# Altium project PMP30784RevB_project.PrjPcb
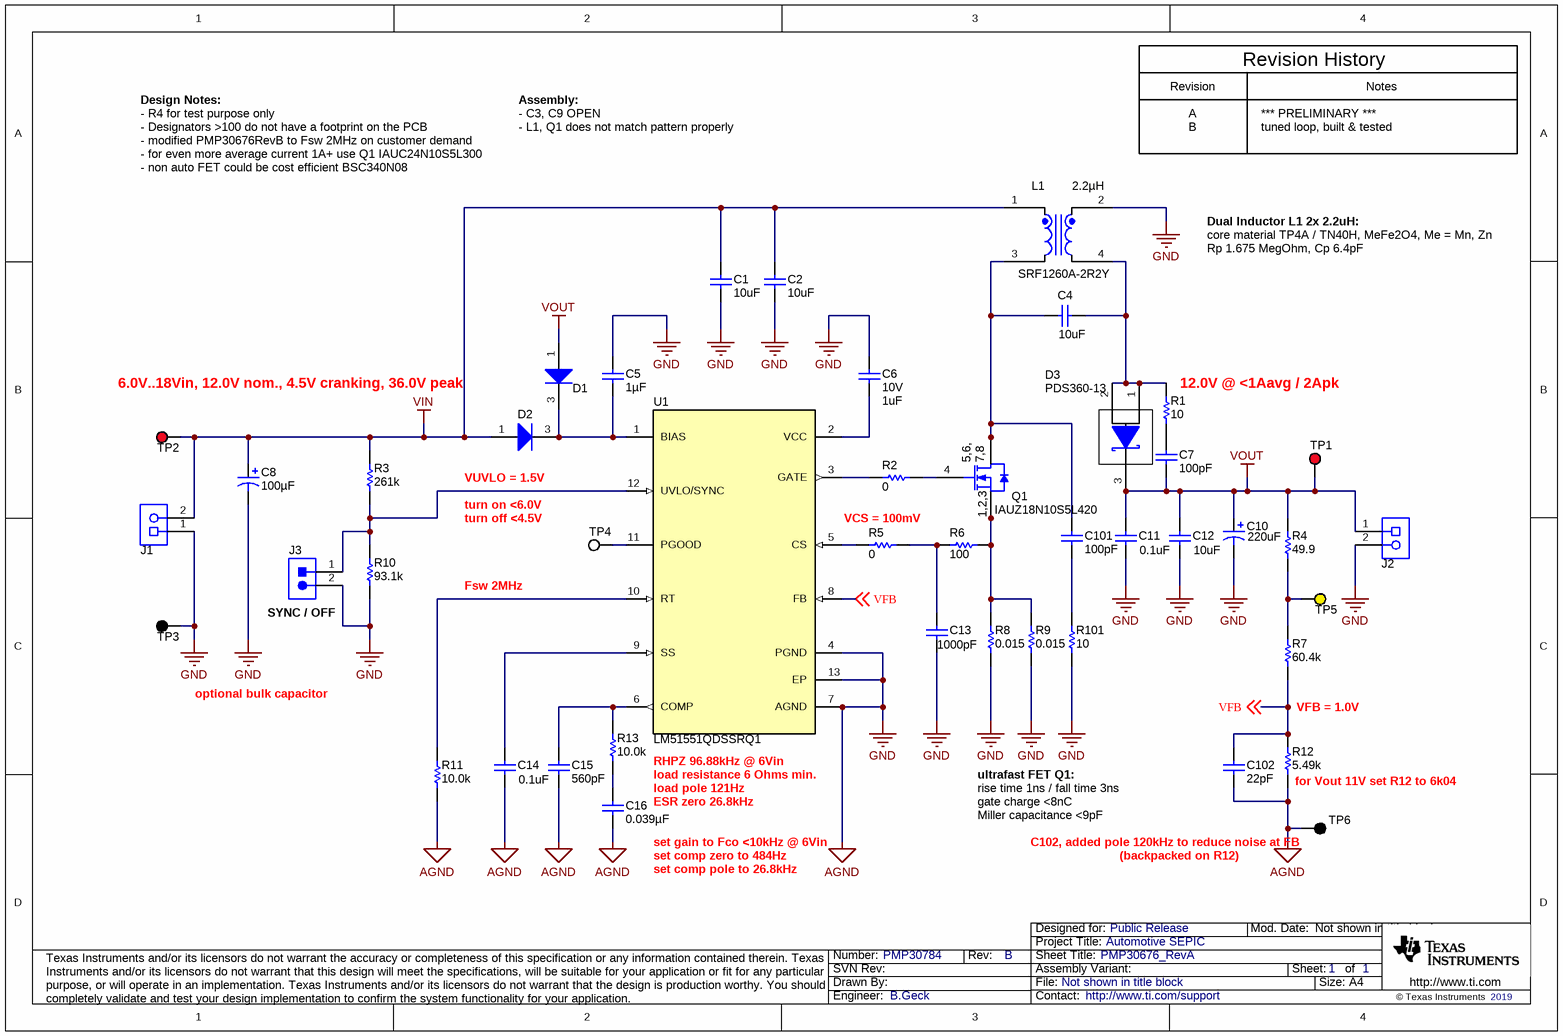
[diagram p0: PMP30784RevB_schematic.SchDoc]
CopyrightYear: 2019; PCB_Layout: M.Zehendner; PCB_Rev: A; PRJ_Customer: Public Release; PRJ_Engineer: B.Geck; PRJ_Number: PMP30784; PRJ_Title: Automotive SEPIC; SCH_Rev: B; TechSupport: http://www.ti.com/support; TID: N/A
1 sheet, 45 parts. Net scope: global (net labels, ports and power ports of the same name join across sheets).
Board file: PMP30676_board.PcbDoc

## Sheet PMP30784RevB_schematic.SchDoc: PMP30676_RevA
size A4; Date: Not shown in title block; ApprovedBy: Not shown in title block; CheckedBy: Not shown in title block; Author: Not shown in title block; CompanyName: Not shown in title block; Engineer: Not shown in title block; Organization: Not shown in title block; Address1: Not shown in title block; Address2: Not shown in title block; Address3: Not shown in title block; Address4: Not shown in title block; DocumentNumber: 1; Revision: Use project parameter SCH_Rev; SheetNumber: 1; SheetTotal: 1; PageSetup: Record=PageOptions¦CenterHorizontal=True¦CenterVertical=True¦PrintScale=0.70¦XCorrection=1.00¦YCorrection=1.00¦PrintKind=0¦BorderSize=5000000¦LeftOffset=0¦BottomOffset=0¦Orientation=2¦PaperLength=1000¦PaperWidth=1000¦Scale=100¦PaperSource=15¦PrintQuality=600¦MediaType=1¦DitherType=10¦PaperKind=A4¦PrintScaleMode=1

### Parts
C1  ValueDisplayed: 10uF  [1210_270]  (hidden comment: GRM32ER71H106KA12L)
C2  ValueDisplayed: 10uF  [1210_270]  (hidden comment: GRM32ER71H106KA12L)
C4  ValueDisplayed: 10uF  [1210_270]  (hidden comment: GRM32ER71H106KA12L)
C5  Cap_F: 1µF  [0805_HV]  (hidden comment: GRM21BR71H105KA12L)
C6  VDC_V: 10V  ValueDisplayed: 1uF  [0805_HV]  (hidden comment: GRM21BR71A105KA01L)
C7  ValueDisplayed: 100pF  [0603]  (hidden comment: GCM1885C2A101JA16D)
C8  ValueDisplayed: 100µF  [Panasonic_G]  (hidden comment: EEH-ZC1H101P)
C10  ValueDisplayed: 220uF  [HXB_HA0]  (hidden comment: HHXC250ARA221MHA0G)
C11  ValueDisplayed: 0.1uF  [0402]  (hidden comment: GRM155R71H104ME14D)
C12  ValueDisplayed: 10uF  [1210_220]  (hidden comment: GRM32DR71E106KA12L)
C13  ValueDisplayed: 1000pF  [0402]  (hidden comment: GRM155R61E102KA01D)
C14  ValueDisplayed: 0.1uF  [0402]  (hidden comment: GRM155R71C104KA88D)
C15  ValueDisplayed: 560pF  [0603]  (hidden comment: GRM1885C1E561JA01D)
C16  ValueDisplayed: 0.039µF  [0603]  (hidden comment: GRM188R71E393KA01D)
C101  ValueDisplayed: 100pF  [0603]  (hidden comment: GCM1885C2A101JA16D)
C102  ValueDisplayed: 22pF  [0603]  (hidden comment: GRM1885C1H220JA01D)
D1  BAS16LT1G  [SOT-23]  (value not drawn)
D2  BAS16LT1G  [SOT-23]  (value not drawn)
D3  PDS360-13  [PowerDI5]
J1  ED120/2DS  [On-Shore_ED120_2DS]  (value not drawn)
J2  ED120/2DS  [On-Shore_ED120_2DS]  (value not drawn)
J3  TSW-102-07-G-S  [TSW-102-07-G-S]  (value not drawn)
L1  SRF1260A-2R2Y  ValueDisplayed: 2.2µH  [SRF1260A]
Q1  IAUZ18N10S5L420  [PG-TSDSON-8FL]
R1  ValueDisplayed: 10  [0805_HV]  (hidden comment: CRCW080510R0JNEA)
R2  ValueDisplayed: 0  [0603]  (hidden comment: ERJ-3GEY0R00V)
R3  ValueDisplayed: 261k  [0603]  (hidden comment: CRCW0603261KFKEA)
R4  ValueDisplayed: 49.9  [0603]  (hidden comment: CRCW060349R9FKEA)
R5  ValueDisplayed: 0  [0603]  (hidden comment: ERJ-3GEY0R00V)
R6  ValueDisplayed: 100  [0603]  (hidden comment: CRCW0603100RFKEA)
R7  ValueDisplayed: 60.4k  [0603]  (hidden comment: CRCW060360K4FKEA)
R8  ValueDisplayed: 0.015  [1206]  (hidden comment: CSR1206FK15L0)
R9  ValueDisplayed: 0.015  [1206]  (hidden comment: CSR1206FK15L0)
R10  ValueDisplayed: 93.1k  [0603]  (hidden comment: CRCW060393K1FKEA)
R11  ValueDisplayed: 10.0k  [0603]  (hidden comment: CRCW060310K0FKEA)
R12  ValueDisplayed: 5.49k  [0603]  (hidden comment: CRCW06035K49FKEA)
R13  ValueDisplayed: 10.0k  [0603]  (hidden comment: CRCW060310K0FKEA)
R101  ValueDisplayed: 10  [0603]  (hidden comment: CRCW060310R0JNEAHP)
TP1  5010  [Keystone5010]  (value not drawn)
TP2  5010  [Keystone5010]  (value not drawn)
TP3  5011  [Keystone5011]  (value not drawn)
TP4  5012  [Keystone5012]  (value not drawn)
TP5  5014  [Keystone5014]  (value not drawn)
TP6  5011  [Keystone5011]  (value not drawn)
U1  LM51551QDSSRQ1  [DSS0012C]

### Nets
AGND: C1.2 C2.2 C5.1 C6.2 C8.2(-) C10.2(-) C11.2 C12.2 C13.2 C14.2 C15.2 C16.2 C102.2 J1.1 J2.2 J3.2 L1.2 R8.1 R9.1 R10.1 R11.1 R12.1 R101.1 TP3.1 TP6.1 U1.4(PGND) U1.7(AGND) U1.13(EP)  [also labelled GND]
VIN: C1.1 C2.1 C8.1(+) D2.1(A) J1.2 L1.1 R3.2 TP2.1
VOUT: C7.2 C10.1(+) C11.1 C12.1 D1.1(A) D3.3(K) J2.1 R4.2 TP1.1
VFB: C102.1 R7.1 R12.2 U1.8(FB) ; off-sheet VFB
NetC4_1: C4.1 D3.1(A) D3.2(A) L1.4 R1.2
NetC4_2: C4.2 C101.1 L1.3 Q1.5(D) Q1.6(D) Q1.7(D) Q1.8(D) Q1.9(D)
NetC5_2: C5.2 D1.3(K) D2.3(K) U1.1(BIAS)
NetC6_1: C6.1 U1.2(VCC)
NetC7_1: C7.1 R1.1
NetC13_1: C13.1 R5.2 R6.1
NetC14_1: C14.1 U1.9(SS)
NetC15_1: C15.1 R13.2 U1.6(COMP)
NetC16_1: C16.1 R13.1
NetC101_2: C101.2 R101.2
NetJ3_1: J3.1 R3.1 R10.2 U1.12(UVLO/SYNC)
NetQ1_1: Q1.1(S) Q1.2(S) Q1.3(S) R6.2 R8.2 R9.2
NetQ1_4: Q1.4(G) R2.2
NetR2_1: R2.1 U1.3(GATE)
NetR4_1: R4.1 R7.2 TP5.1
NetR5_1: R5.1 U1.5(CS)
NetR11_2: R11.2 U1.10(RT)
NetTP4_1: TP4.1 U1.11(PGOOD)

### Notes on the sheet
- Design Notes:
- - R4 for test purpose only
- Assembly:
- - C3, C9 OPEN
- Revision
- A
- *** PRELIMINARY ***
- Revision History
- Notes
- - Designators >100 do not have a footprint on the PCB
- - modified PMP30676RevB to Fsw 2MHz on customer demand
- - for even more average current 1A+ use Q1 IAUC24N10S5L300
- - non auto FET could be cost efficient BSC340N08
- - L1, Q1 does not match pattern properly
- B
- tuned loop, built & tested
- Dual Inductor L1 2x 2.2uH:
- core material TP4A / TN40H, MeFe2O4, Me = Mn, Zn
- Rp 1.675 MegOhm, Cp 6.4pF
- 6.0V..18Vin, 12.0V nom., 4.5V cranking, 36.0V peak
- (near R1) 12.0V @ <1Aavg / 2Apk
- (near D2) VUVLO = 1.5V
- turn on <6.0V
- turn off <4.5V
- VCS = 100mV
- Fsw 2MHz
- (near J3) SYNC / OFF
- optional bulk capacitor
- VFB = 1.0V
- RHPZ 96.88kHz @ 6Vin
- load resistance 6 Ohms min.
- load pole 121Hz
- ultrafast FET Q1:
- rise time 1ns / fall time 3ns
- (near R12) for Vout 11V set R12 to 6k04
- (near C16) set gain to Fco <10kHz @ 6Vin
- (near C16) set comp zero to 484Hz
- ESR zero 26.8kHz
- gate charge <8nC
- Miller capacitance <9pF
- (backpacked on R12)
- (near TP6) C102, added pole 120kHz to reduce noise at FB
- set comp pole to 26.8kHz

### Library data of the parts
C1 C2 C4 = CMP-0009226-3: CAP, CERM, 10 uF, 50 V, +/- 10%, X7R, 1210; Manufacturer: MuRata; TaMin_C: -55°C; Polarized: N; SizeAreaWB_mm2: 14.7; Value1: Unknown; U/M: EA; Value: 10uF; TaMax_C: 125°C; SizeZ_mm: 2.7; SizeX_mm: 3.2; SizeY_mm: 2.5; Cap_Case: 1210; Value2: 50V; SizeArea_mm2: 8; Cap_F: 10µF; AEC Category: Q200
C5 = CMP-0008350-2: CAP, CERM, 1 uF, 50 V, +/- 10%, X7R, 0805; Manufacturer: MuRata; TaMin_C: -55°C; Polarized: N; SizeAreaWB_mm2: 6.75; Value1: Unknown; U/M: EA; Value: 1uF; TaMax_C: 125°C; SizeZ_mm: 1.45; SizeX_mm: 2; SizeY_mm: 1.25; Cap_Case: 0805; Value2: 50V; SizeArea_mm2: 2.5; AEC Category: Q200
C6 = CMP-0008313-2: CAP, CERM, 1 uF, 10 V, +/- 10%, X7R, 0805; Manufacturer: MuRata; TaMin_C: -55°C; ESR_ohm: 7m; Polarized: N; SizeAreaWB_mm2: 6.75; Value1: 0.007 ohm; U/M: EA; Value: 1uF; TaMax_C: 125°C; SizeZ_mm: 1.45; SizeX_mm: 2; SizeY_mm: 1.25; Cap_Case: 0805; SizeArea_mm2: 2.5; Cap_F: 1µF; AEC Category: Q200
C7 C101 = GCM1885C2A101JA16D: CAP, CERM, 100 pF, 100 V,+/- 5%, C0G/NP0, AEC-Q200 Grade 1, 0603; Manufacturer: MuRata; Polarized: N; CompType: Capacitor; Value: 100pF; U/M: EA; Cap_F: 0.0000000001; Tolerance_%: 5; VDC_V: 100; Value2: 100V; TaMin_C: -55; TaMax_C: 125; SizeArea_mm2: 1.28; SizeAreaWB_mm2: 4.68; SizeX_mm: 1.6; SizeY_mm: 0.8; SizeZ_mm: 1; AEC Category: Q200; AEC Qualified: Y
C8 = EEH-ZC1H101P: CAP, Polymer Hybrid, 100 µF, 50 V,+/- 20%, 0.028 ohm, AEC-Q200 Grade 1, D10xL10.2mm SMD; Manufacturer: Panasonic; Polarized: Y; CompType: Capacitor; Value: 100uF; U/M: EA; Cap_F: 0.0001; Tolerance_%: 20; VDC_V: 50; Value2: 50V; ESR_ohm: 0.028; IRMS_A: 1.6; TaMin_C: -55; TaMax_C: 125; Cap_Case: 10x10.2mm; SizeAreaWB_mm2: 151.29; SizeArea_mm2: 106.09; SizeX_mm: 10.3; SizeZ_mm: 10.5; AEC Category: Q200; AEC Grade: 1
C10 = CMP-0012270-3: CAP, Aluminum Polymer, 220 uF, 25 V, +/- 20%, 0.027 ohm, AEC-Q200 Grade 2, D8xL10mm SMD; Manufacturer: Chemi-Con; TaMin_C: -55°C; ESR_ohm: 0.03; Polarized: Y; SizeAreaWB_mm2: 113.3; Value: 220uF; TaMax_C: 105°C; SizeZ_mm: 10.5; SizeX_mm: 9; SizeY_mm: 8.3; Cap_Case: HA0; Value2: 25V; SizeArea_mm2: 74.7; CompType: Capacitor; Cap_F: 220µF; IRMS_A: 1.6A; AEC Grade: 2; AEC Category: Q200
C11 = CMP-0006675-2: CAP, CERM, 0.1 uF, 50 V, +/- 20%, X7R, 0402; Manufacturer: MuRata; TaMin_C: -55°C; Polarized: N; SizeAreaWB_mm2: 3; Value1: Unknown; U/M: EA; Value: 0.1uF; TaMax_C: 125°C; SizeZ_mm: 0.6; SizeX_mm: 1; SizeY_mm: 0.5; Value2: 50V; Cap_F: 100nF; AEC Category: Q200
C12 = CMP-0009190-2: CAP, CERM, 10 uF, 25 V, +/- 10%, X7R, 1210; Manufacturer: MuRata; TaMin_C: -55°C; Polarized: N; SizeAreaWB_mm2: 14.7; Value1: Unknown; U/M: EA; Value: 10uF; TaMax_C: 125°C; SizeZ_mm: 2.2; SizeX_mm: 3.2; SizeY_mm: 2.5; Cap_Case: 1210; Value2: 25V; SizeArea_mm2: 8; Cap_F: 10µF; AEC Category: Q200
C13 = CMP-0006606-2: CAP, CERM, 1000 pF, 25 V, +/- 10%, X5R, 0402; Manufacturer: MuRata; TaMin_C: -55°C; Polarized: N; SizeAreaWB_mm2: 3; Value1: Unknown; U/M: EA; Value: 1000pF; TaMax_C: 85°C; SizeZ_mm: 0.6; SizeX_mm: 1; SizeY_mm: 0.5; Value2: 25V; Cap_F: 1nF; AEC Category: Q200
C14 = CMP-0006641-2: CAP, CERM, 0.1 uF, 16 V, +/- 10%, X7R, 0402; Manufacturer: MuRata; TaMin_C: -55°C; Polarized: N; SizeAreaWB_mm2: 3; Value1: Unknown; U/M: EA; Value: 0.1uF; TaMax_C: 125°C; SizeZ_mm: 0.6; SizeX_mm: 1; SizeY_mm: 0.5; Value2: 16V; Cap_F: 100nF; AEC Category: Q200
C15 = GRM1885C1E561JA01D: CAP, CERM, 560 pF, 25 V,+/- 5%, C0G/NP0, 0603; Manufacturer: MuRata; Polarized: N; CompType: Capacitor; Value: 560pF; U/M: EA; Cap_F: 0.00000000056; Tolerance_%: 5; VDC_V: 25; Value2: 25V; TaMin_C: -55; TaMax_C: 125; SizeArea_mm2: 1.28; SizeAreaWB_mm2: 4.68; SizeX_mm: 1.6; SizeY_mm: 0.8; SizeZ_mm: 1; AEC Category: Q200
C16 = GRM188R71E393KA01D: CAP, CERM, 0.039 µF, 25 V,+/- 10%, X7R, 0603; Manufacturer: MuRata; Polarized: N; CompType: Capacitor; Value: 0.039uF; U/M: EA; Cap_F: 0.000000039; Tolerance_%: 10; VDC_V: 25; Value2: 25V; TaMin_C: -55; TaMax_C: 125; SizeArea_mm2: 1.28; SizeAreaWB_mm2: 4.68; SizeX_mm: 1.6; SizeY_mm: 0.8; SizeZ_mm: 1; AEC Category: Q200
C102 = GRM1885C1H220JA01D: CAP, CERM, 22 pF, 50 V,+/- 5%, C0G/NP0, 0603; Manufacturer: MuRata; Polarized: N; CompType: Capacitor; Value: 22pF; U/M: EA; Cap_F: 0.000000000022; Tolerance_%: 5; VDC_V: 50; Value2: 50V; TaMin_C: -55; TaMax_C: 125; SizeArea_mm2: 1.28; SizeAreaWB_mm2: 4.68; SizeX_mm: 1.6; SizeY_mm: 0.8; SizeZ_mm: 1; AEC Category: Q200; Green_Lifecycle: Active; Green_REACh: Passed
D1 D2 = CMP-0029193-2: Diode, Switching, 100 V, 0.2 A, SOT-23; Manufacturer: ON Semiconductor; Value: 100V; Green_Lifecycle: Active; SizeAreaWB_mm2: 14; Vf_V: 1.25V; SizeZ_mm: 1.1; AEC Qualified: N; SizeX_mm: 2.5; Green_REACh: Passed; AEC Category: Q101; Value1: 0.2A; SizeY_mm: 3; SizeArea_mm2: 7.5; Io_A: 200mA; TJmax_C: 150°C
D3 = PDS360-13: Diode, Schottky, 60 V, 3 A, PowerDI5; Manufacturer: Diodes Inc.; U/M: EA; Vf_V: 0.62; Value: 60V; Value1: 3A; Value2: 0.62V; Io_A: 3; Vr_V: 60; TJmax_C: 150; SizeAreaWB_mm2: 49.56; SizeArea_mm2: 24.96; SizeX_mm: 6.4; SizeY_mm: 3.9; SizeZ_mm: 1.05; AEC Category: Q101; Green_Lifecycle: Active; Green_REACh: Passed
J1 J2 = CMP-0074910-1: Terminal Block, 5.08 mm, 2x1, Brass, TH; Manufacturer: On-Shore Technology; Cert_VDE: Y; CNHeader: False; Current_A: 15A; Green_Lifecycle: Not Set; Shrouded: N; Gender: Female; Green_REACh: Incomplete; Voltage_V: 300V; Row_Count: 1; Pitch_mm: 5.08; CT: True
J3 = CMP-0075405-2: Header, 100mil, 2x1, Gold, TH; Manufacturer: Samtec; Pitch_mm: 2.54; Cert_VDE: N; Gender: Male; Cert_CSA: Y; Voltage_V: 550V; Green_REACh: Passed; Current_A: 6.3A; Green_Lifecycle: Active; Row_Count: 1
L1 = SRF1260A-331M: Coupled inductor, 2.2 µH, 5.44A, 0.009 ohm, AEC-Q200 Grade 1, SMD; Manufacturer: Bourns; SymbolCreator: a0412235; SizeAreaWB_mm2: 210.25; SizeArea_mm2: 156.25; SizeX_mm: 12.5; SizeZ_mm: 6.2; Value: 2.2uH; Ind_H: 2.2E-6; DCR_ohm: 0.009; AEC Category: Q200; AEC Qualified: Y; AEC Grade: 1
Q1 = BSZ013NE2LS5IATMA1: MOSFET, N-CH, 100 V, 40 A, 8-PG-TSDSON; Manufacturer: Infineon Technologies; Alternate Manufacturer: None; U/M: EA; ChType: N; Value: 100V; VdsMax_V: 100; Value1: 0.055 ohm; Rdson45_ohm: 0.055; Value2: 5.4 nC; QgTyp_nC: 5.4; Vgs_V: 20; IdsMax_A: 18; SizeAreaWB_mm2: 18.49; SizeArea_mm2: 10.89; SizeX_mm: 3.3; SizeZ_mm: 1.1; AEC Category: Q101; AEC Qualified: Y; Green_Lifecycle: Active; Green_REACh: Passed
R1 = CRCW080510R0JNEA: RES, 10, 5%, 0.125 W, 0805; Manufacturer: Vishay-Dale; CompType: Resistor; Value: 10; Value_Code: 10R0; Tolerance_%: 5; Power_W: 0.125; Value2: 0.125W; VDC_V: 150; TempCo: 200 ppm/C; SizeArea_mm2: 2.5; SizeX_mm: 2; SizeY_mm: 1.25; SizeZ_mm: 1.45; EIA_Code: E24; U/M: EA; AEC Category: Q200; Green_Lifecycle: Active; Green_REACh: Passed
R2 R5 = CMP-0025874-4: RES, 0, 5%, 0.1 W, AEC-Q200 Grade 0, 0603; Manufacturer: Panasonic; Power_W: 100mW; TempCo: 600 ppm/C; Value_Code: 0000; Value: 0; EIA_Code: E24; SizeX_mm: 1.6; SizeY_mm: 0.8; SizeZ_mm: 1; Value2: 0.1W; SizeArea_mm2: 1.28; AEC Qualified: Y; VDC_V: 50V; AEC Category: Q200; SizeAreaWB_mm2: 4.68
R3 = CMP-0022244-4: RES, 261 k, 1%, 0.1 W, AEC-Q200 Grade 0, 0603; Manufacturer: Vishay-Dale; Power_W: 100mW; TempCo: 100 ppm/C; Value: 261k; EIA_Code: E96; SizeX_mm: 1.6; SizeY_mm: 0.8; SizeZ_mm: 1; Value2: 0.1W; SizeArea_mm2: 1.28; AEC Qualified: Y; VDC_V: 75V; AEC Category: Q200; AEC Grade: 0
R4 = CMP-0022448-4: RES, 49.9, 1%, 0.1 W, AEC-Q200 Grade 0, 0603; Manufacturer: Vishay-Dale; Power_W: 100mW; TempCo: 100 ppm/C; Value_Code: 49R9; Value: 49.9; EIA_Code: E96; SizeX_mm: 1.6; SizeY_mm: 0.8; SizeZ_mm: 1; Value2: 0.1W; SizeArea_mm2: 1.28; AEC Qualified: Y; VDC_V: 75V; AEC Category: Q200; AEC Grade: 0
R6 = CMP-0021991-2: RES, 100, 1%, 0.1 W, 0603; Manufacturer: Vishay-Dale; Power_W: 100mW; TempCo: 100 ppm/C; Value_Code: 100R; U/M: EA; Value: 100; EIA_Code: E96; SizeX_mm: 1.6; SizeY_mm: 0.8; SizeZ_mm: 1; Value2: 0.1W; SizeArea_mm2: 1.28; VDC_V: 75V; AEC Category: Q200
R7 = CMP-0022532-4: RES, 60.4 k, 1%, 0.1 W, AEC-Q200 Grade 0, 0603; Manufacturer: Vishay-Dale; Power_W: 100mW; TempCo: 100 ppm/C; Value_Code: 60k4; Value: 60.4k; EIA_Code: E96; SizeX_mm: 1.6; SizeY_mm: 0.8; SizeZ_mm: 1; Value2: 0.1W; SizeArea_mm2: 1.28; AEC Qualified: Y; VDC_V: 75V; AEC Category: Q200; AEC Grade: 0
R8 R9 = CMP-0017258-2: RES, 0.015, 1%, 0.5 W, 1206; Manufacturer: Stackpole Electronics Inc; Power_W: 500mW; TempCo: 100 ppm/C; Value_Code: R015; U/M: EA; Value: 0.015; EIA_Code: E96; SizeX_mm: 3.2; SizeY_mm: 1.6; SizeZ_mm: 1.35; Value2: 0.5W; SizeArea_mm2: 5.12; AEC Category: Q200
R10 = CMP-0022655-4: RES, 93.1 k, 1%, 0.1 W, AEC-Q200 Grade 0, 0603; Manufacturer: Vishay-Dale; Power_W: 100mW; TempCo: 100 ppm/C; Value_Code: 93k1; Value: 93.1k; EIA_Code: E96; SizeX_mm: 1.6; SizeY_mm: 0.8; SizeZ_mm: 1; Value2: 0.1W; SizeArea_mm2: 1.28; AEC Qualified: Y; VDC_V: 75V; AEC Category: Q200; AEC Grade: 0
R11 R13 = CRCW060310K0FKEA: RES, 10.0 k, 1%, 0.1 W, 0603; Manufacturer: Vishay-Dale; CompType: Resistor; Value: 10.0k; Res_ohm: 10000; Value_Code: 10k0; Tolerance_%: 1; Power_W: 0.1; Value2: 0.1W; VDC_V: 75; TempCo: 100 ppm/C; SizeArea_mm2: 1.28; SizeX_mm: 1.6; SizeY_mm: 0.8; EIA_Code: E96; U/M: EA; AEC Category: Q200; Green_Lifecycle: Active; Green_REACh: Passed
R12 = CMP-0022512-4: RES, 5.49 k, 1%, 0.1 W, AEC-Q200 Grade 0, 0603; Manufacturer: Vishay-Dale; Power_W: 100mW; TempCo: 100 ppm/C; Value_Code: 5k49; Value: 5.49k; EIA_Code: E96; SizeX_mm: 1.6; SizeY_mm: 0.8; SizeZ_mm: 1; Value2: 0.1W; SizeArea_mm2: 1.28; AEC Qualified: Y; VDC_V: 75V; AEC Category: Q200; AEC Grade: 0
R101 = CRCW060310R0JNEAHP: RES, 10, 5%, 0.25 W, 0603; Manufacturer: Vishay-Dale; CompType: Resistor; Value: 10; Value_Code: 10R0; Tolerance_%: 5; Power_W: 0.25; Value2: 0.25W; VDC_V: 75; TempCo: 200 ppm/C; SizeArea_mm2: 1.28; SizeX_mm: 1.6; SizeY_mm: 0.8; SizeZ_mm: 1; EIA_Code: E24; U/M: EA; AEC Category: Q200; Green_Lifecycle: Active; Green_REACh: Passed
TP1 TP2 = CMP-0055147-1: Test Point, Multipurpose, Red, TH; Manufacturer: Keystone; CNHeader: FALSE; Green_Lifecycle: Active; Green_REACh: Passed; ContactFinish: Silver; CT: TRUE
TP3 TP6 = CMP-0055148-1: Test Point, Multipurpose, Black, TH; Manufacturer: Keystone; CNHeader: FALSE; Green_Lifecycle: Active; Green_REACh: Passed; ContactFinish: Silver; CT: TRUE
TP4 = CMP-0055149-1: Test Point, Multipurpose, White, TH; Manufacturer: Keystone; CNHeader: FALSE; Green_Lifecycle: Active; Green_REACh: Passed; ContactFinish: Silver; CT: TRUE
TP5 = CMP-0055151-1: Test Point, Multipurpose, Yellow, TH; Manufacturer: Keystone; CNHeader: FALSE; Green_Lifecycle: Active; Green_REACh: Passed; ContactFinish: Silver; CT: TRUE
U1 = CMP-0081541-1: Automotive Grade 2.2-MHz Wide Input Non-synchronous Boost Controller, DSS0012C (WSON-12); Alternate PartNumber: LM51551QDSSTQ1; Alternate Manufacturer: Texas Instruments; SizeAreaWB_mm2: 12; SizeZ_mm: 0.8; SizeX_mm: 2; SizeY_mm: 3; SizeArea_mm2: 6; CompType: IC; AEC Qualified: Y; AEC Category: Q200

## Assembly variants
001: not fitted FID1 FID2 FID3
